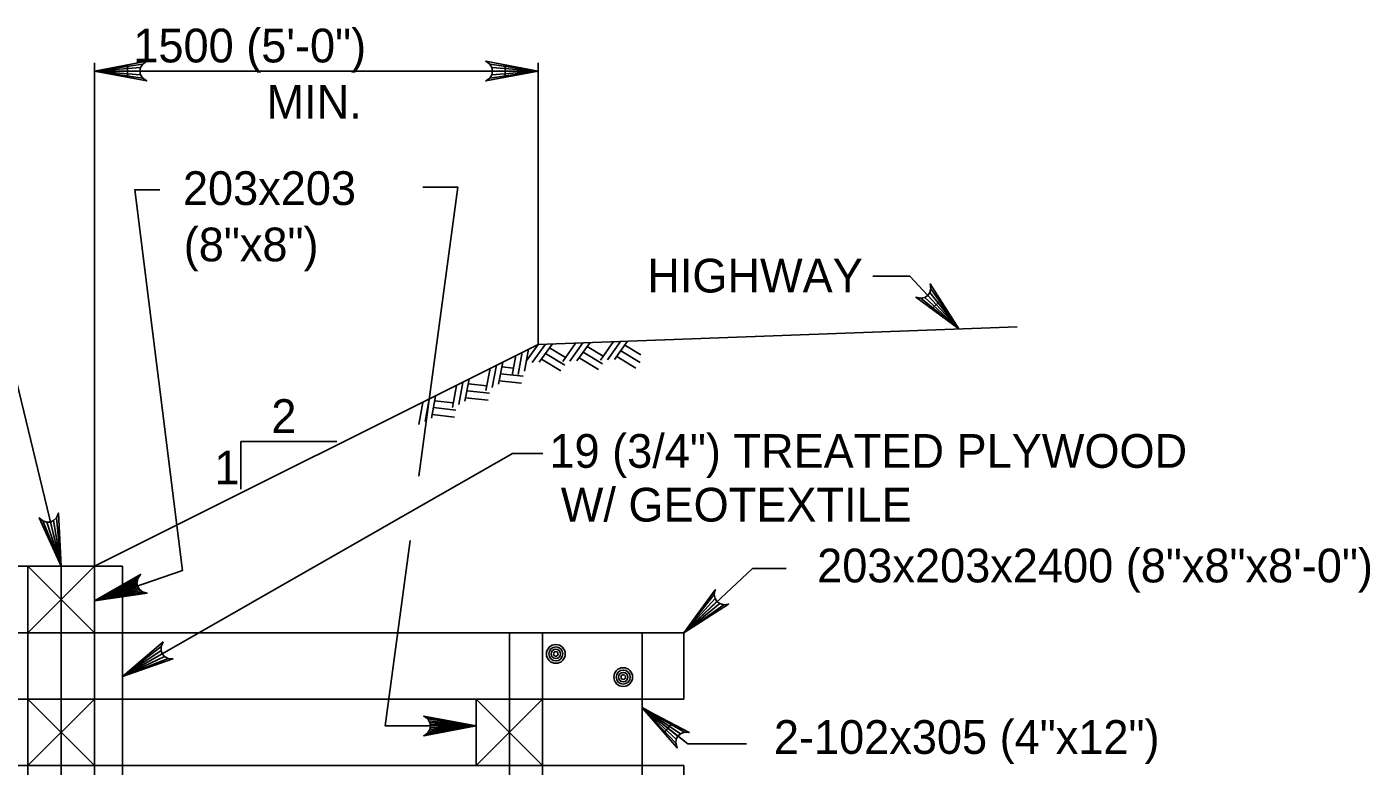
# Model space of a CAD drawing. Extents: x 638142 to 639291, y 297247 to 298438.
# Drawn here: x 638906.2 to 639025.7, y 298073.2 to 298139 of the extents above; entities that cross this region are included whole.
import ezdxf

# ---------------------------------------------------------------- set-up
doc = ezdxf.new("R2010")
doc.units = 0
for name, color, linetype in [('3', 7, 'Continuous'), ('5', 7, 'Continuous'), ('52', 7, 'Continuous')]:
    doc.layers.add(name, color=color, linetype=linetype)

msp = doc.modelspace()

# ---------------------------------------------------------------- linework, layer by layer
at = {"layer": '3'}
for p, q in [((638951.68, 298110.74), (638994.28, 298112.3)), ((638951.68, 298110.74), (638912.21, 298091)), ((638951.68, 298110.74), (638950.62, 298109.24)), ((638952.32, 298110.76), (638951.15, 298109.12)), ((638952.94, 298110.78), (638951.78, 298109.15)), ((638955.03, 298110.86), (638953.87, 298109.22)), ((638955.66, 298110.88), (638954.5, 298109.24)), ((638956.29, 298110.9), (638955.13, 298109.27)), ((638958.37, 298110.98), (638957.21, 298109.34)), ((638959.01, 298111), (638957.84, 298109.36)), ((638959.63, 298111.02), (638958.47, 298109.39)), ((638959.39, 298110.68), (638960.81, 298109.82)), ((638949.7, 298109.74), (638949.37, 298108.01)), ((638950.26, 298110.03), (638949.89, 298108.05)), ((638950.82, 298110.31), (638950.45, 298108.34)), ((638952.33, 298109.92), (638954.05, 298108.88)), ((638952.7, 298110.44), (638954.12, 298109.58)), ((638955.31, 298109.53), (638957.03, 298108.49)), ((638955.68, 298110.04), (638957.39, 298109)), ((638956.04, 298110.56), (638957.46, 298109.7)), ((638958.66, 298109.65), (638960.37, 298108.61)), ((638959.02, 298110.16), (638960.74, 298109.12)), ((638947.41, 298108.59), (638947.03, 298106.62)), ((638947.97, 298108.88), (638947.6, 298106.9)), ((638948.53, 298109.16), (638948.16, 298107.19)), ((638948.45, 298108.74), (638949.49, 298108.63)), ((638951.97, 298109.41), (638953.68, 298108.37)), ((638944.42, 298107.08), (638944.05, 298105.11)), ((638944.98, 298107.36), (638944.61, 298105.39)), ((638945.54, 298107.65), (638945.17, 298105.68)), ((638945.47, 298107.24), (638947.12, 298107.05)), ((638948.22, 298107.5), (638950.21, 298107.28)), ((638948.34, 298108.12), (638950.33, 298107.9)), ((638941.99, 298105.86), (638941.62, 298103.89)), ((638942.56, 298106.14), (638942.18, 298104.17)), ((638945.23, 298105.99), (638947.22, 298105.77)), ((638945.35, 298106.61), (638947.34, 298106.39)), ((638941.43, 298105.57), (638941.06, 298103.6)), ((638942.36, 298105.11), (638944.35, 298104.88)), ((638942.48, 298105.73), (638944.13, 298105.54)), ((638942.24, 298104.49), (638944.23, 298104.26)), ((638897.44, 298091), (638906.3, 298091)), ((638906.3, 298091), (638906.3, 298085.09)), ((638906.3, 298085.09), (638912.21, 298091)), ((638906.3, 298091), (638912.21, 298085.09)), ((638906.3, 298091), (638914.72, 298091)), ((638909.25, 298091), (638909.25, 298015.59)), ((638912.21, 298091), (638912.21, 298014.22)), ((638914.72, 298091), (638914.72, 298025.25)), ((638912.21, 298085.09), (638897.44, 298085.09)), ((638912.21, 298085.09), (638906.3, 298085.09)), ((638906.3, 298085.09), (638906.3, 298014.22)), ((638906.3, 298085.09), (638912.21, 298085.09)), ((638952.07, 298085.09), (638912.21, 298085.09)), ((638912.21, 298085.09), (638914.42, 298085.09)), ((638949.12, 298085.09), (638949.12, 298046.07)), ((638952.07, 298085.09), (638964.62, 298085.09)), ((638952.07, 298085.09), (638952.07, 298025.11)), ((638960.93, 298085.09), (638960.93, 298043.75)), ((638964.62, 298085.09), (638964.62, 298079.18)), ((638912.21, 298079.18), (638897.44, 298079.18)), ((638906.3, 298079.18), (638912.21, 298079.18)), ((638906.3, 298079.18), (638912.21, 298073.28)), ((638906.3, 298073.28), (638912.21, 298079.18)), ((638906.3, 298079.18), (638906.3, 298073.28)), ((638912.21, 298079.18), (638952.07, 298079.18)), ((638912.21, 298079.18), (638912.21, 298073.28)), ((638946.16, 298079.18), (638946.16, 298073.28)), ((638946.16, 298073.28), (638952.07, 298079.18)), ((638946.16, 298079.18), (638952.07, 298073.28)), ((638946.16, 298079.18), (638952.07, 298079.18)), ((638952.07, 298079.18), (638952.07, 298073.28)), ((638960.93, 298079.18), (638952.07, 298079.18)), ((638952.07, 298079.18), (638960.93, 298079.18)), ((638960.93, 298079.18), (638964.62, 298079.18)), ((638960.93, 298079.18), (638960.93, 298014.22)), ((638897.44, 298073.28), (638906.3, 298073.28)), ((638912.21, 298073.28), (638906.3, 298073.28)), ((638906.3, 298073.28), (638912.21, 298073.28)), ((638952.07, 298073.28), (638906.3, 298073.28)), ((638946.16, 298073.28), (638952.07, 298073.28)), ((638952.07, 298073.28), (638960.93, 298073.28)), ((638964.62, 298073.28), (638960.93, 298073.28)), ((638964.62, 298073.28), (638964.62, 298067.37))]:
    msp.add_line(p, q, dxfattribs=at)
for centre, radius in [((638953.25, 298083.21), 0.833), ((638953.25, 298083.21), 0.625), ((638953.25, 298083.21), 0.417), ((638953.25, 298083.21), 0.208), ((638959.24, 298081.15), 0.833), ((638959.24, 298081.15), 0.625), ((638959.24, 298081.15), 0.417), ((638959.24, 298081.15), 0.208)]:
    msp.add_circle(centre, radius, dxfattribs=at)
at = {"layer": '5'}
for p, q in [((638912.21, 298091), (638912.21, 298135.78)), ((638951.68, 298110.74), (638951.68, 298135.78)), ((638951.68, 298135.04), (638912.21, 298135.04)), ((638984.72, 298116.81), (638981.45, 298116.81)), ((638989.08, 298112.11), (638984.72, 298116.81)), ((638925.25, 298102.09), (638933.76, 298102.09)), ((638925.25, 298097.87), (638925.25, 298102.09)), ((638914.72, 298081.21), (638949.39, 298101.02)), ((638949.39, 298101.02), (638952.08, 298101.02)), ((638964.62, 298085.09), (638970.73, 298090.82)), ((638970.73, 298090.82), (638973.73, 298090.82)), ((638960.93, 298078.43), (638965, 298075.2)), ((638965, 298075.2), (638970.2, 298075.2))]:
    msp.add_line(p, q, dxfattribs=at)
for points in [[(638912.21, 298135.04), (638916.87, 298135.91), (638916.51, 298135.66), (638916.32, 298135.35), (638916.27, 298135.04), (638916.32, 298134.72), (638916.51, 298134.41), (638916.87, 298134.16), (638912.21, 298135.04), (638916.51, 298134.41), (638916.32, 298134.72), (638912.21, 298135.04), (638916.27, 298135.04), (638916.32, 298135.35), (638912.21, 298135.04), (638916.51, 298135.66)], [(638951.68, 298135.04), (638947.02, 298134.16), (638947.38, 298134.41), (638947.57, 298134.72), (638947.62, 298135.04), (638947.57, 298135.35), (638947.38, 298135.66), (638947.02, 298135.91), (638951.68, 298135.04), (638947.38, 298135.66), (638947.57, 298135.35), (638951.68, 298135.04), (638947.62, 298135.04), (638947.57, 298134.72), (638951.68, 298135.04), (638947.38, 298134.41)], [(638909.25, 298091), (638902.15, 298120.35), (638896.04, 298120.35)], [(638989.08, 298112.11), (638985.27, 298114.93), (638985.7, 298114.84), (638986.05, 298114.91), (638986.32, 298115.09), (638986.51, 298115.34), (638986.61, 298115.69), (638986.55, 298116.12), (638989.08, 298112.11), (638986.61, 298115.69), (638986.51, 298115.34), (638989.08, 298112.11), (638986.32, 298115.09), (638986.05, 298114.91), (638989.08, 298112.11), (638985.7, 298114.84)], [(638909.25, 298091), (638907.31, 298095.32), (638907.63, 298095.03), (638907.98, 298094.92), (638908.3, 298094.94), (638908.59, 298095.07), (638908.85, 298095.32), (638909.01, 298095.73), (638909.25, 298091), (638908.85, 298095.32), (638908.59, 298095.07), (638909.25, 298091), (638908.3, 298094.94), (638907.98, 298094.92), (638909.25, 298091), (638907.63, 298095.03)], [(638964.62, 298085.09), (638967.42, 298088.91), (638967.33, 298088.49), (638967.41, 298088.13), (638967.58, 298087.87), (638967.83, 298087.68), (638968.18, 298087.58), (638968.61, 298087.64), (638964.62, 298085.09), (638968.18, 298087.58), (638967.83, 298087.68), (638964.62, 298085.09), (638967.58, 298087.87), (638967.41, 298088.13), (638964.62, 298085.09), (638967.33, 298088.49)], [(638914.72, 298081.21), (638918.33, 298084.28), (638918.15, 298083.88), (638918.14, 298083.52), (638918.25, 298083.22), (638918.45, 298082.98), (638918.77, 298082.8), (638919.2, 298082.76), (638914.72, 298081.21), (638918.77, 298082.8), (638918.45, 298082.98), (638914.72, 298081.21), (638918.25, 298083.22), (638918.14, 298083.52), (638914.72, 298081.21), (638918.15, 298083.88)], [(638960.93, 298078.43), (638965.12, 298076.22), (638964.69, 298076.24), (638964.35, 298076.11), (638964.11, 298075.9), (638963.96, 298075.62), (638963.91, 298075.27), (638964.03, 298074.85), (638960.93, 298078.43), (638963.91, 298075.27), (638963.96, 298075.62), (638960.93, 298078.43), (638964.11, 298075.9), (638964.35, 298076.11), (638960.93, 298078.43), (638964.69, 298076.24)]]:
    msp.add_lwpolyline(points, dxfattribs=at)
for points in [[(638915.16, 298134.54), (638915.16, 298135.53), (638912.21, 298135.04)], [(638948.73, 298134.54), (638948.73, 298135.53), (638951.68, 298135.04)], [(638987.43, 298114.61), (638986.71, 298113.94), (638989.08, 298112.11)], [(638963.54, 298076.99), (638962.92, 298076.22), (638960.92, 298078.44)]]:
    msp.add_lwpolyline(points, close=True, dxfattribs=at)
at = {"layer": '52'}
for points in [[(638912.21, 298087.94), (638920.04, 298090.62), (638915.81, 298124.49), (638918.03, 298124.49)], [(638941.07, 298099.01), (638944.54, 298124.71), (638941.42, 298124.71)], [(638946.16, 298076.8), (638938.08, 298076.8), (638940.3, 298093.31)], [(638912.21, 298087.94), (638916.33, 298090.28), (638916.2, 298090.1), (638916.07, 298089.92), (638916.04, 298089.75), (638916, 298089.57), (638916.03, 298089.41), (638916.05, 298089.26), (638916.13, 298089.12), (638916.2, 298088.98), (638916.34, 298088.86), (638916.48, 298088.74), (638916.69, 298088.68), (638916.9, 298088.62), (638912.21, 298087.94), (638916.69, 298088.68), (638916.48, 298088.74), (638912.21, 298087.94), (638916.34, 298088.86), (638916.2, 298088.98), (638912.21, 298087.94), (638916.13, 298089.12), (638916.05, 298089.26), (638912.21, 298087.94), (638916.03, 298089.41), (638916, 298089.57), (638912.21, 298087.94), (638916.04, 298089.75), (638916.07, 298089.92), (638912.21, 298087.94), (638916.2, 298090.1)], [(638946.16, 298076.8), (638941.5, 298075.93), (638941.68, 298076.05), (638941.86, 298076.18), (638941.95, 298076.33), (638942.05, 298076.49), (638942.07, 298076.64), (638942.1, 298076.8), (638942.07, 298076.96), (638942.05, 298077.11), (638941.95, 298077.27), (638941.86, 298077.43), (638941.68, 298077.55), (638941.5, 298077.67), (638946.16, 298076.8), (638941.68, 298077.55), (638941.86, 298077.43), (638946.16, 298076.8), (638941.95, 298077.27), (638942.05, 298077.11), (638946.16, 298076.8), (638942.07, 298076.96), (638942.1, 298076.8), (638946.16, 298076.8), (638942.07, 298076.64), (638942.05, 298076.49), (638946.16, 298076.8), (638941.95, 298076.33), (638941.86, 298076.18), (638946.16, 298076.8), (638941.68, 298076.05)]]:
    msp.add_lwpolyline(points, dxfattribs=at)

# ---------------------------------------------------------------- texts
at = {"layer": '5'}
for s, height, p in [('1500 (5\'-0")', 3.0001, (638915.68, 298135.81)), ('MIN.', 3, (638927.52, 298130.81)), ('203x203', 3, (638920.09, 298123.13)), ('(8"x8")', 3, (638920.16, 298118.12)), ('HIGHWAY', 3, (638961.38, 298115.35)), ('2', 3, (638927.95, 298102.86)), ('19 (3/4") TREATED PLYWOOD', 3.0001, (638952.68, 298099.76)), ('1', 3, (638922.89, 298098.28)), ('W/ GEOTEXTILE', 3.0001, (638953.69, 298094.98)), ('203x203x2400 (8"x8"x8\'-0")', 3.0001, (638976.49, 298089.57)), ('2-102x305 (4"x12")', 3.0001, (638972.64, 298074.32))]:
    msp.add_text(s, height=height, dxfattribs=at).set_placement(p)

doc.saveas('drawing.dxf')
